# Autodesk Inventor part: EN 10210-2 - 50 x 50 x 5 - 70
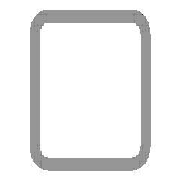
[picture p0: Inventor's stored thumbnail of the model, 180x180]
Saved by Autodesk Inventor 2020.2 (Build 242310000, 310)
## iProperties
IsCustomPart: 1
_CCFamilyMember: 16
_CCFamilyDisplayName: DIN EN 10210-2 (USAS B17.1 quadratisch) - Rohrleitung — In Klammern angegebene Größen wurden aufgehoben
_FrameMemberDoc: Frame Member File
_Version: 15.0.0
_GetPNFromCC: 1
Created: 2019-10
Part Number: EN 10210-2 - 50 x 50 x 5 - 70
Material: Stahl, weich
Description: Rohrleitung
Document SubType Name: Modeling
Standard: DIN
Designer: lutzd
Standard Revision: 2006-07
Standards Organization: DIN
Language: de-DE
Size Designation: 50 x 50 x 5
Categories: <MemberInstance><Categories><Category DisplayName="Profile" InternalName="089c4875-fa83-4c05-b084-43b9cc11f5ed" Mnemonic="GRDR"><CategoryParameter DisplayName="
Stock Number: 50 x 50 x 5
Mass: 479.81 g
Surface Area: 254.441 cm^2
Volume: 61.1222 cm^3
Density: 7.85 g/cm^3
Appearance: Semi-Polished(8)
G_L: 70,000 mm
G_W: 50,000 mm
G_H: 50,000 mm
Dimensions: 50x50x70 mm
Mass: 0,48 kg
DocNumber: ADSK-014291
Folder: .
+6D058FE3-8CB6-4A1D-ACC9-1BBEF0A54B61+SCHNITTDETAIL1: Schnittwinkel 90,00 grd
VLT_Material: Stahl, weich
Title: Profil-Bauteil
Author: lutzd
Revision Number: -
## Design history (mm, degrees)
node "Startebene"
node "Endebene"
sketch "Skizze"
  geometry: L1 (-25, -17.5)-(-25, 17.5); L2 (-17.5, 25)-(17.5, 25); L3 (25, 17.5)-(25, -17.5); L4 (17.5, -25)-(-17.5, -25); L5 (-15, 20)-(15, 20); L6 (20, 15)-(20, -15); L7 (15, -20)-(-15, -20); L8 (-20, -15)-(-20, 15); L9 (0, 37.175)-(0, -37.175) reference; L10 (-37.175, 0)-(37.175, 0) reference; A1 r 7.5 centre (-17.5, -17.5) between (-25, -17.5) and (-17.5, -25); A2 r 7.5 centre (-17.5, 17.5) between (-17.5, 25) and (-25, 17.5); A3 r 7.5 centre (17.5, 17.5) between (25, 17.5) and (17.5, 25); A4 r 7.5 centre (17.5, -17.5) between (17.5, -25) and (25, -17.5); A5 r 5 centre (-15, -15) between (-20, -15) and (-15, -20); A6 r 5 centre (-15, 15) between (-15, 20) and (-20, 15); A7 r 5 centre (15, 15) between (20, 15) and (15, 20); A8 r 5 centre (15, -15) between (15, -20) and (20, -15)
  constraints: 16 end point, 16 point on circle, 16 tangent, 8 centre point, 6 equal radius, 4 parallel, 2 perpendicular, 2 other
  dimensions: "d7" = 7.5 radius of A1 (= G_IR); "d10" = 50 distance between parallel lines of L2 L4 (= G_H); "d11" = 50 distance between parallel lines of L1 L3 (= G_W); "d12" = 5 distance between parallel lines of L3 L6 (= G_T); "d15" = 25 distance between parallel lines of L2 L10 (= 0.5 x d10); "d16" = 25 distance between parallel lines of L9 L3 (= 0.5 x d11); "d19" = 5 radius of A5 (= G_T); "d20" = 5 distance between parallel lines of L4 L7 (= G_T)
extrude "Körper" new body sketch "Skizze" stored distance "d3" = 70 (= G_L); taper "d4" = 0 deg
node "Driven Length"
  sketch "Sketch3"
    geometry: L1 (0, 0)-(10, 0) reference
    constraints: 2 end point, 1 horizontal
  workplane "Work Plane3"
  sketch "Sketch4"
    geometry: L1 (-2, 25)-(12, 25) reference; L2 (-2, 95)-(12, 95) reference
    dimensions: "d18" = 70 distance between parallel lines of L1 L2 (derived)
workplane "Arbeitsebene4"
feature "Trennen1"
body "Solid1"
other parameters: "G_W" = 50 [user parameter; used in 1 equation term], "G_H" = 50 [user parameter; used in 1 equation term], "G_T" = 5 [user parameter; used in 3 equation terms], "G_IR" = 7.5 [user parameter; used in 1 equation term], "G_L" = 70 (= d18) [user parameter; used in 1 equation term], "G_OFFSET_START" = -25 [user parameter; used in 1 equation term], "G_OFFSET_END" = 0 [user parameter; used in 1 equation term], "d13" = 25 (= -G_OFFSET_START), "d14" = 95 (= G_OFFSET_END + B_L), "B_L" = 95 [user parameter; used in 1 equation term], "d17" = 90 deg
